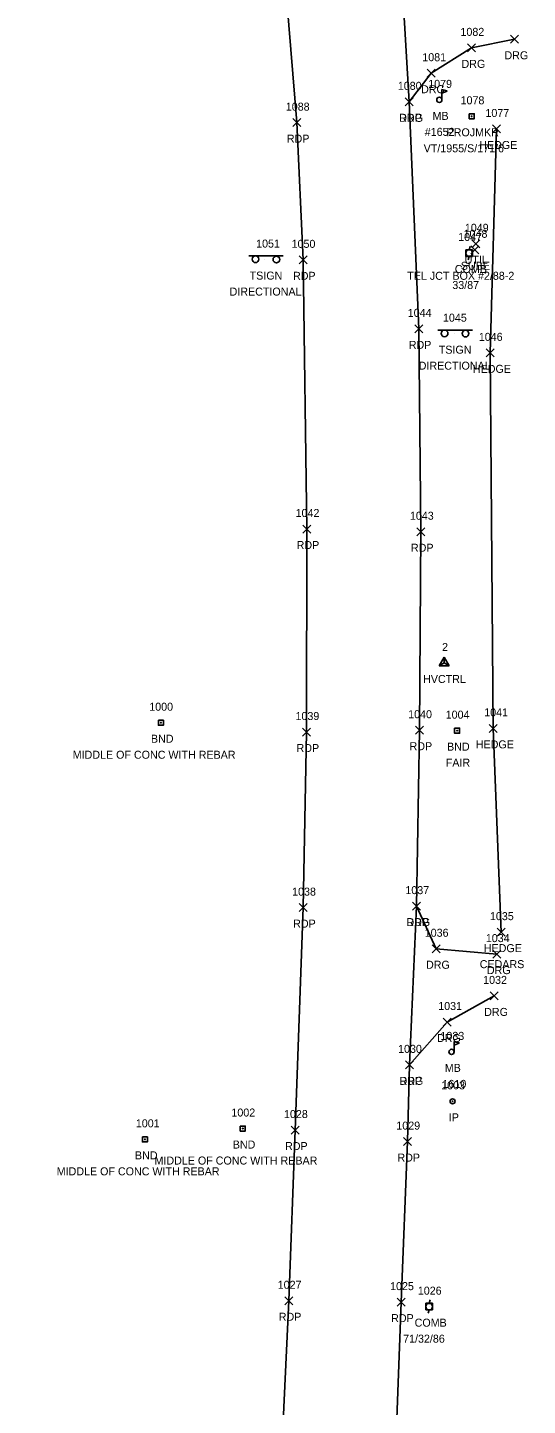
# Model space of a CAD drawing. Extents: x 1496556 to 1498241, y 599216 to 604470.
# Drawn here: x 1497213.5 to 1497338.5, y 602380.7 to 602725.1 of the extents above; entities that cross this region are included whole.
import ezdxf

# ---------------------------------------------------------------- set-up
doc = ezdxf.new("R2010")
doc.units = 0
for name, color, linetype in [('C_A', 7, 'Continuous'), ('C_I', 7, 'Continuous'), ('CPSM', 7, 'Continuous'), ('L_A', 7, 'Continuous'), ('L_C', 7, 'Continuous'), ('L_I', 7, 'Continuous'), ('L_TIC', 7, 'Continuous'), ('LAHR', 7, 'Continuous'), ('Level 18', 7, 'Continuous'), ('LMB', 7, 'Continuous'), ('M_A', 7, 'Continuous'), ('M_C', 7, 'Continuous'), ('M_I', 7, 'Continuous'), ('MPIR', 7, 'Continuous'), ('P_A', 7, 'Continuous'), ('P_I', 7, 'Continuous'), ('P_TIC', 7, 'Continuous'), ('PET', 7, 'Continuous'), ('R_A', 7, 'Continuous'), ('R_I', 7, 'Continuous'), ('R_TIC', 7, 'Continuous'), ('RDG', 7, 'Continuous'), ('S_A', 7, 'Continuous'), ('S_C', 7, 'Continuous'), ('S_I', 7, 'Continuous'), ('SRM', 7, 'Continuous'), ('SSGN', 7, 'Continuous'), ('U_A', 7, 'Continuous'), ('U_C', 7, 'Continuous'), ('U_I', 7, 'Continuous'), ('U_TIC', 7, 'Continuous'), ('UDEFAULT', 7, 'Continuous'), ('UP', 7, 'Continuous')]:
    doc.layers.add(name, color=color, linetype=linetype)

msp = doc.modelspace()

# ---------------------------------------------------------------- linework, layer by layer
at = {"layer": 'CPSM'}
for p, q in [((1497316.46, 602565.57), (1497317.71, 602567.73)), ((1497316.46, 602565.57), (1497317.71, 602566.29)), ((1497316.46, 602565.57), (1497318.96, 602565.57)), ((1497318.96, 602565.57), (1497317.71, 602567.73)), ((1497317.71, 602566.29), (1497317.71, 602567.73)), ((1497317.71, 602566.29), (1497317.71, 602566.29)), ((1497317.71, 602566.29), (1497318.96, 602565.57))]:
    msp.add_line(p, q, dxfattribs=at)
at = {"layer": 'L_TIC'}
for points in [[(1497329.76, 602698.78), (1497331.76, 602700.78)], [(1497331.76, 602698.78), (1497329.76, 602700.78)], [(1497328.16, 602642.82), (1497330.16, 602644.82)], [(1497330.16, 602642.82), (1497328.16, 602644.82)], [(1497328.89, 602548.95), (1497330.89, 602550.95)], [(1497330.89, 602548.95), (1497328.89, 602550.95)], [(1497330.89, 602498.01), (1497332.89, 602500.01)], [(1497332.89, 602498.01), (1497330.89, 602500.01)]]:
    msp.add_lwpolyline(points, dxfattribs=at)
at = {"layer": 'LAHR'}
msp.add_lwpolyline([(1497331.89, 602499.01), (1497329.89, 602549.95), (1497329.16, 602643.82), (1497330.76, 602699.78)], dxfattribs=at)
at = {"layer": 'Level 18'}
for points in [[(1497246.26, 602551.99), (1497247.51, 602551.99), (1497247.51, 602550.74), (1497246.26, 602550.74)], [(1497320.28, 602550), (1497321.53, 602550), (1497321.53, 602548.75), (1497320.28, 602548.75)], [(1497242.26, 602447.84), (1497243.51, 602447.84), (1497243.51, 602446.59), (1497242.26, 602446.59)], [(1497266.72, 602450.54), (1497267.97, 602450.54), (1497267.97, 602449.29), (1497266.72, 602449.29)]]:
    msp.add_lwpolyline(points, close=True, dxfattribs=at)
for centre in [(1497246.89, 602551.36), (1497320.91, 602549.38), (1497267.34, 602449.92), (1497242.89, 602447.22)]:
    msp.add_circle(centre, 0.0833, dxfattribs=at)
at = {"layer": 'LMB'}
for p, q in [((1497317.12, 602709.66), (1497318.41, 602709.28)), ((1497317.12, 602707.07), (1497317.12, 602709.66)), ((1497316.47, 602707.06), (1497316.47, 602707.06)), ((1497317.12, 602708.76), (1497318.4, 602709.27)), ((1497319.52, 602469.08), (1497319.52, 602469.08)), ((1497320.17, 602471.68), (1497321.47, 602471.3)), ((1497320.18, 602469.09), (1497320.18, 602471.68)), ((1497320.18, 602470.78), (1497321.46, 602471.29))]:
    msp.add_line(p, q, dxfattribs=at)
for centre in [(1497316.47, 602707.06), (1497319.52, 602469.08)]:
    msp.add_circle(centre, 0.656, dxfattribs=at)
at = {"layer": 'MPIR'}
for radius in [0.625, 0.0833]:
    msp.add_circle((1497319.78, 602456.72), radius, dxfattribs=at)
at = {"layer": 'P_TIC'}
for points in [[(1497307.95, 602705.57), (1497309.95, 602707.57)], [(1497309.95, 602705.57), (1497307.95, 602707.57)], [(1497279.87, 602700.36), (1497281.87, 602702.36)], [(1497281.87, 602700.36), (1497279.87, 602702.36)], [(1497281.4, 602666.07), (1497283.4, 602668.07)], [(1497283.4, 602666.07), (1497281.4, 602668.07)], [(1497310.34, 602648.82), (1497312.34, 602650.82)], [(1497312.34, 602648.82), (1497310.34, 602650.82)], [(1497282.31, 602598.78), (1497284.31, 602600.78)], [(1497284.31, 602598.78), (1497282.31, 602600.78)], [(1497310.88, 602598.1), (1497312.88, 602600.1)], [(1497312.88, 602598.1), (1497310.88, 602600.1)], [(1497282.29, 602548.03), (1497284.29, 602550.03)], [(1497284.29, 602548.03), (1497282.29, 602550.03)], [(1497310.54, 602548.49), (1497312.54, 602550.49)], [(1497312.54, 602548.49), (1497310.54, 602550.49)], [(1497309.76, 602504.51), (1497311.76, 602506.51)], [(1497311.76, 602504.51), (1497309.76, 602506.51)], [(1497281.45, 602504.14), (1497283.45, 602506.14)], [(1497283.45, 602504.14), (1497281.45, 602506.14)], [(1497308.02, 602464.84), (1497310.02, 602466.84)], [(1497310.02, 602464.84), (1497308.02, 602466.84)], [(1497279.41, 602448.54), (1497281.41, 602450.54)], [(1497281.41, 602448.54), (1497279.41, 602450.54)], [(1497307.5, 602445.65), (1497309.5, 602447.65)], [(1497309.5, 602445.65), (1497307.5, 602447.65)], [(1497277.84, 602405.87), (1497279.84, 602407.87)], [(1497279.84, 602405.87), (1497277.84, 602407.87)], [(1497305.93, 602405.52), (1497307.93, 602407.52)], [(1497307.93, 602405.52), (1497305.93, 602407.52)]]:
    msp.add_lwpolyline(points, dxfattribs=at)
at = {"layer": 'PET'}
for points in [[(1497255.35, 601840.33), (1497260.72, 601945.51), (1497260.6, 601945.5), (1497265.21, 602060.91), (1497267.76, 602124.12), (1497271.3, 602209.29), (1497274.95, 602307.82), (1497276.81, 602364.31), (1497278.84, 602406.87), (1497280.41, 602449.54), (1497282.45, 602505.14), (1497283.29, 602549.03), (1497283.31, 602599.78), (1497282.4, 602667.07), (1497280.87, 602701.36), (1497277.35, 602744.02), (1497266.99, 602833.93), (1497261.25, 602868.44), (1497249.2, 602924.4), (1497241.75, 602954.09), (1497234.18, 602981.9), (1497224.39, 603014.86), (1497221.77, 603020.8), (1497213.53, 603046.79)], [(1497283.3, 601836.85), (1497288.13, 601944.77), (1497293.47, 602059.45), (1497296.19, 602123.28), (1497299.59, 602207.66), (1497303.16, 602306.06), (1497305.27, 602361.72), (1497306.93, 602406.52), (1497308.5, 602446.65), (1497309.02, 602465.84), (1497310.76, 602505.51), (1497311.54, 602549.49), (1497311.88, 602599.1), (1497311.34, 602649.82), (1497308.95, 602706.57), (1497306.6, 602746.03), (1497301.66, 602792.87), (1497295.53, 602839.35), (1497290.13, 602872.5), (1497283.12, 602906.81), (1497277.08, 602932.51)]]:
    msp.add_lwpolyline(points, dxfattribs=at)
at = {"layer": 'R_TIC'}
for points in [[(1497323.52, 602719.06), (1497325.52, 602721.06)], [(1497325.52, 602719.06), (1497323.52, 602721.06)], [(1497334.26, 602721.2), (1497336.26, 602723.2)], [(1497336.26, 602721.2), (1497334.26, 602723.2)], [(1497313.42, 602712.72), (1497315.42, 602714.72)], [(1497315.42, 602712.72), (1497313.42, 602714.72)], [(1497307.95, 602705.57), (1497309.95, 602707.57)], [(1497309.95, 602705.57), (1497307.95, 602707.57)], [(1497309.76, 602504.51), (1497311.76, 602506.51)], [(1497311.76, 602504.51), (1497309.76, 602506.51)], [(1497314.65, 602493.86), (1497316.65, 602495.86)], [(1497316.65, 602493.86), (1497314.65, 602495.86)], [(1497329.86, 602492.52), (1497331.86, 602494.52)], [(1497331.86, 602492.52), (1497329.86, 602494.52)], [(1497329.19, 602482.07), (1497331.19, 602484.07)], [(1497331.19, 602482.07), (1497329.19, 602484.07)], [(1497317.39, 602475.55), (1497319.39, 602477.55)], [(1497319.39, 602475.55), (1497317.39, 602477.55)], [(1497308.02, 602464.84), (1497310.02, 602466.84)], [(1497310.02, 602464.84), (1497308.02, 602466.84)]]:
    msp.add_lwpolyline(points, dxfattribs=at)
at = {"layer": 'RDG'}
for points in [[(1497308.95, 602706.57), (1497314.42, 602713.72), (1497324.52, 602720.06), (1497335.26, 602722.2)], [(1497330.86, 602493.52), (1497315.65, 602494.86), (1497310.76, 602505.51)], [(1497309.02, 602465.84), (1497318.39, 602476.55), (1497330.19, 602483.07)]]:
    msp.add_lwpolyline(points, dxfattribs=at)
at = {"layer": 'SRM'}
msp.add_lwpolyline([(1497323.93, 602703.58), (1497325.18, 602703.58), (1497325.18, 602702.33), (1497323.93, 602702.33)], close=True, dxfattribs=at)
msp.add_circle((1497324.55, 602702.95), 0.0833, dxfattribs=at)
at = {"layer": 'SSGN'}
for p, q in [((1497268.85, 602668.05), (1497277.45, 602668.05)), ((1497272.88, 602667.14), (1497272.88, 602667.14)), ((1497316.13, 602649.53), (1497324.73, 602649.53)), ((1497320.15, 602648.62), (1497320.15, 602648.62))]:
    msp.add_line(p, q, dxfattribs=at)
for centre in [(1497270.51, 602667.21), (1497275.73, 602667.14), (1497317.79, 602648.69), (1497323.01, 602648.62)]:
    msp.add_circle(centre, 0.833, dxfattribs=at)
at = {"layer": 'U_TIC'}
for points in [[(1497324.31, 602668.58), (1497326.31, 602670.58)], [(1497326.31, 602668.58), (1497324.31, 602670.58)]]:
    msp.add_lwpolyline(points, dxfattribs=at)
at = {"layer": 'UDEFAULT'}
for points in [[(1497324.63, 602670.08), (1497326.63, 602672.08)], [(1497326.63, 602670.08), (1497324.63, 602672.08)]]:
    msp.add_lwpolyline(points, dxfattribs=at)
at = {"layer": 'UP'}
for p, q in [((1497323.12, 602667.94), (1497323.12, 602669.61)), ((1497323.12, 602669.61), (1497324.78, 602669.61)), ((1497324.2, 602670.44), (1497323.95, 602669.61)), ((1497323.95, 602668.78), (1497323.95, 602668.78)), ((1497324.78, 602669.61), (1497324.78, 602667.94)), ((1497324.78, 602667.94), (1497323.12, 602667.94)), ((1497323.7, 602667.11), (1497323.95, 602667.94)), ((1497314.16, 602407.06), (1497313.91, 602406.23)), ((1497313.08, 602404.56), (1497313.08, 602406.23)), ((1497313.08, 602406.23), (1497314.75, 602406.23)), ((1497314.75, 602404.56), (1497313.08, 602404.56)), ((1497313.66, 602403.73), (1497313.91, 602404.56)), ((1497313.91, 602405.39), (1497313.91, 602405.39)), ((1497314.75, 602406.23), (1497314.75, 602404.56))]:
    msp.add_line(p, q, dxfattribs=at)
for centre in [(1497323.95, 602668.78), (1497313.91, 602405.39)]:
    msp.add_circle(centre, 0.833, dxfattribs=at)

# ---------------------------------------------------------------- texts
at = {"layer": 'C_A'}
msp.add_text('HVCTRL', height=2, dxfattribs=at).set_placement((1497312.41, 602561.29))
at = {"layer": 'C_I'}
msp.add_text('2', height=2, dxfattribs=at).set_placement((1497317.15, 602569.29))
at = {"layer": 'L_A'}
for s, p in [('MB', (1497314.77, 602702.06)), ('HEDGE', (1497326.46, 602694.78)), ('HEDGE', (1497324.86, 602638.82)), ('HEDGE', (1497325.59, 602544.95)), ('HEDGE', (1497327.59, 602494.01)), ('MB', (1497317.83, 602464.08))]:
    msp.add_text(s, height=2, dxfattribs=at).set_placement(p)
at = {"layer": 'L_C'}
for s, p in [('#1652', (1497312.83, 602698.06)), ('CEDARS', (1497326.57, 602490.01)), ('1610', (1497317.26, 602460.08))]:
    msp.add_text(s, height=2, dxfattribs=at).set_placement(p)
at = {"layer": 'L_I'}
for s, p in [('1079', (1497313.69, 602710.06)), ('1077', (1497327.99, 602702.78)), ('1046', (1497326.34, 602646.82)), ('1041', (1497327.69, 602552.95)), ('1035', (1497329.12, 602502.01)), ('1033', (1497316.75, 602472.08))]:
    msp.add_text(s, height=2, dxfattribs=at).set_placement(p)
at = {"layer": 'M_A'}
for s, p in [('BND', (1497244.38, 602546.36)), ('BND', (1497318.4, 602544.38)), ('IP', (1497318.83, 602451.72)), ('BND', (1497264.83, 602444.92)), ('BND', (1497240.38, 602442.22))]:
    msp.add_text(s, height=2, dxfattribs=at).set_placement(p)
at = {"layer": 'M_C'}
for s, p in [('MIDDLE OF CONC WITH REBAR', (1497224.82, 602542.36)), ('FAIR', (1497318.08, 602540.38)), ('MIDDLE OF CONC WITH REBAR', (1497245.27, 602440.92)), ('MIDDLE OF CONC WITH REBAR', (1497220.82, 602438.22))]:
    msp.add_text(s, height=2, dxfattribs=at).set_placement(p)
at = {"layer": 'M_I'}
for s, p in [('1000', (1497243.95, 602554.36)), ('1004', (1497318.06, 602552.38)), ('1003', (1497316.93, 602459.72)), ('1002', (1497264.49, 602452.92)), ('1001', (1497240.6, 602450.22))]:
    msp.add_text(s, height=2, dxfattribs=at).set_placement(p)
at = {"layer": 'P_A'}
for p in [(1497306.44, 602701.57), (1497278.35, 602696.36), (1497279.89, 602662.07), (1497308.83, 602644.82), (1497280.8, 602594.78), (1497309.37, 602594.1), (1497280.78, 602544.03), (1497309.03, 602544.49), (1497279.93, 602500.14), (1497308.24, 602500.51), (1497306.51, 602460.84), (1497277.9, 602444.54), (1497305.99, 602441.65), (1497276.33, 602401.87), (1497304.42, 602401.52)]:
    msp.add_text('RDP', height=2, dxfattribs=at).set_placement(p)
at = {"layer": 'P_I'}
for s, p in [('1080', (1497306.09, 602709.57)), ('1088', (1497278.09, 602704.36)), ('1050', (1497279.54, 602670.07)), ('1044', (1497308.57, 602652.82)), ('1042', (1497280.54, 602602.78)), ('1043', (1497309.11, 602602.1)), ('1039', (1497280.51, 602552.03)), ('1040', (1497308.68, 602552.49)), ('1038', (1497279.67, 602508.14)), ('1037', (1497307.98, 602508.51)), ('1030', (1497306.16, 602468.84)), ('1028', (1497277.64, 602452.54)), ('1029', (1497305.72, 602449.65)), ('1027', (1497276.07, 602409.87)), ('1025', (1497304.16, 602409.52))]:
    msp.add_text(s, height=2, dxfattribs=at).set_placement(p)
at = {"layer": 'R_A'}
for p in [(1497322.01, 602715.06), (1497332.75, 602717.2), (1497311.9, 602708.72), (1497306.44, 602701.57), (1497308.24, 602500.51), (1497313.14, 602489.86), (1497328.35, 602488.52), (1497327.68, 602478.07), (1497315.88, 602471.55), (1497306.51, 602460.84)]:
    msp.add_text('DRG', height=2, dxfattribs=at).set_placement(p)
at = {"layer": 'R_I'}
for s, p in [('1082', (1497321.75, 602723.06)), ('1081', (1497312.21, 602716.72)), ('1080', (1497306.09, 602709.57)), ('1037', (1497307.98, 602508.51)), ('1036', (1497312.82, 602497.86)), ('1034', (1497328.09, 602496.52)), ('1032', (1497327.42, 602486.07)), ('1031', (1497316.19, 602479.55)), ('1030', (1497306.16, 602468.84))]:
    msp.add_text(s, height=2, dxfattribs=at).set_placement(p)
at = {"layer": 'S_A'}
for s, p in [('PROJMKR', (1497318.28, 602697.95)), ('TSIGN', (1497269.05, 602662.13)), ('TSIGN', (1497316.33, 602643.61))]:
    msp.add_text(s, height=2, dxfattribs=at).set_placement(p)
at = {"layer": 'S_C'}
for s, p in [('VT/1955/S/171/6', (1497312.55, 602693.95)), ('DIRECTIONAL', (1497264.04, 602658.13)), ('DIRECTIONAL', (1497311.31, 602639.61))]:
    msp.add_text(s, height=2, dxfattribs=at).set_placement(p)
at = {"layer": 'S_I'}
for s, p in [('1078', (1497321.78, 602705.95)), ('1051', (1497270.67, 602670.13)), ('1045', (1497317.38, 602651.61))]:
    msp.add_text(s, height=2, dxfattribs=at).set_placement(p)
at = {"layer": 'U_A'}
for s, p in [('COMB', (1497320.34, 602663.78)), ('SUBE', (1497321.85, 602664.58)), ('UTIL', (1497322.8, 602666.08)), ('COMB', (1497310.3, 602400.39))]:
    msp.add_text(s, height=2, dxfattribs=at).set_placement(p)
at = {"layer": 'U_C'}
for s, p in [('TEL JCT BOX #2/88-2', (1497308.45, 602662.08)), ('33/87', (1497319.71, 602659.78)), ('71/32/86', (1497307.42, 602396.39))]:
    msp.add_text(s, height=2, dxfattribs=at).set_placement(p)
at = {"layer": 'U_I'}
for s, p in [('1049', (1497322.85, 602674.08)), ('1047', (1497321.18, 602671.78)), ('1048', (1497322.54, 602672.58)), ('1026', (1497311.09, 602408.39))]:
    msp.add_text(s, height=2, dxfattribs=at).set_placement(p)

doc.saveas('drawing.dxf')
